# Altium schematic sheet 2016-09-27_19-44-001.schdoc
size 468 x 148 mm; SheetNumber: 1; SheetTotal: 1
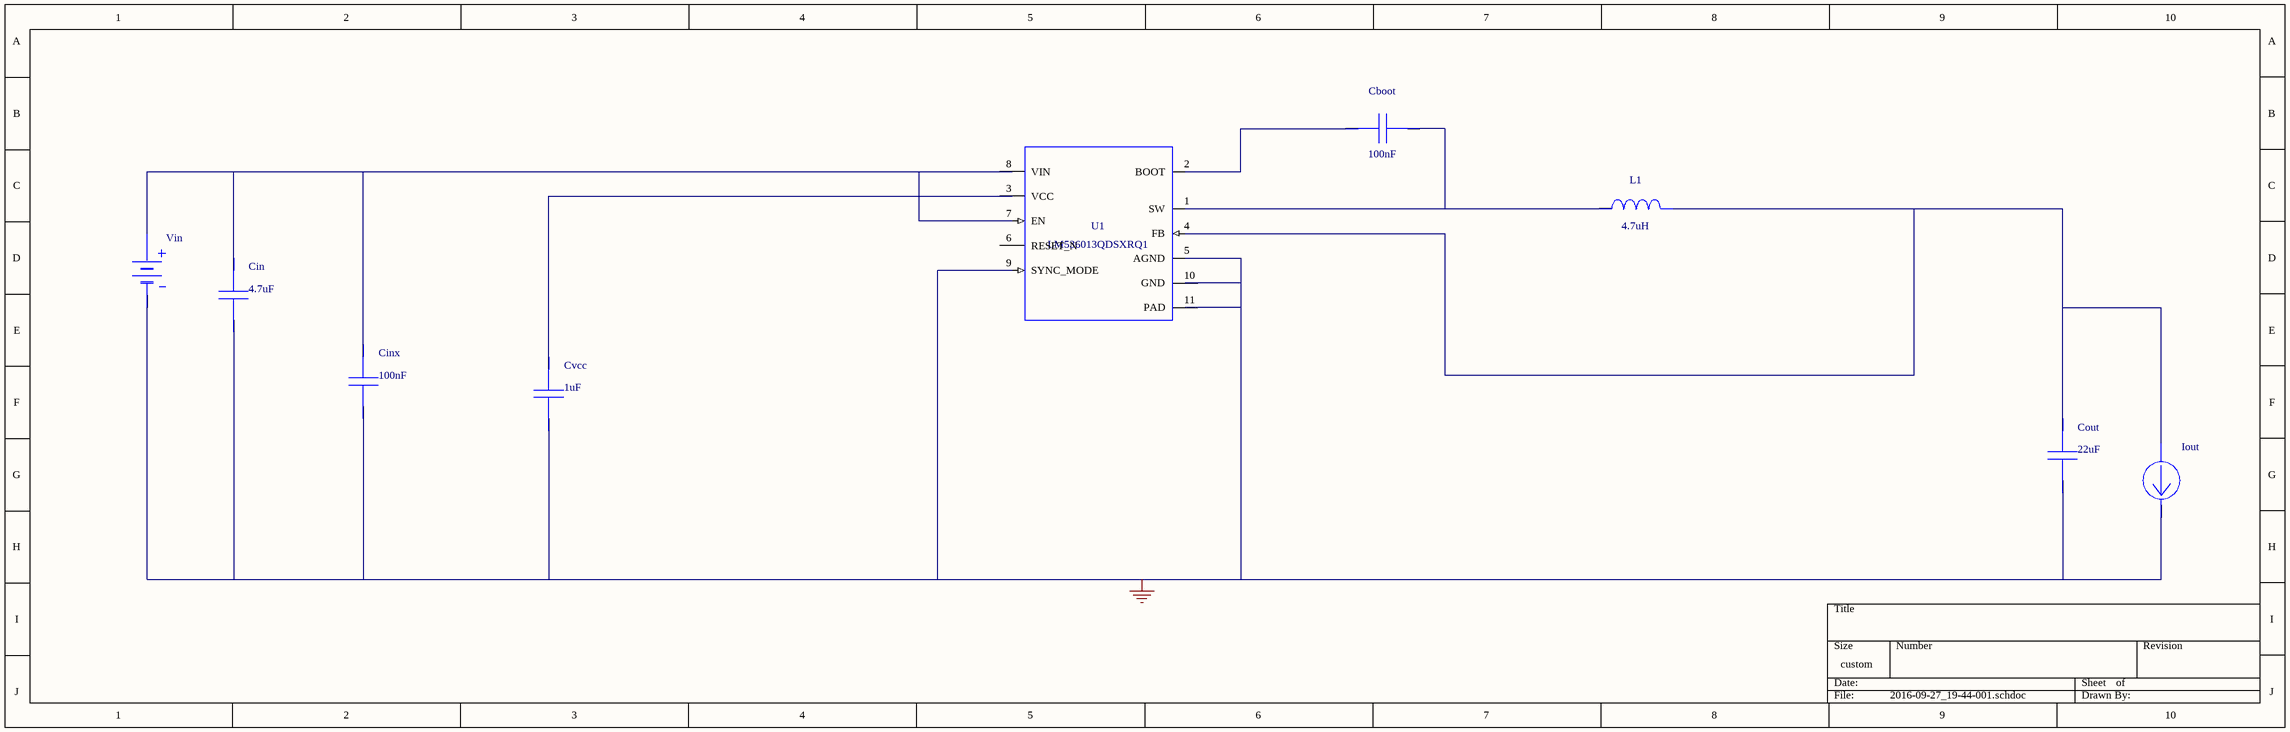
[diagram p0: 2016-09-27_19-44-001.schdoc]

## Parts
Cboot  value 100nF  (hidden comment: C0805C104K5RACTU)
Cin  value 4.7uF  (hidden comment: GRM32ER71H475KA88L)
Cinx  value 100nF  (hidden comment: 08055C104JAT2A)
Cout  value 22uF  (hidden comment: GRM32ER61C226ME20L)
Cvcc  value 1uF  (hidden comment: C1005X5R0J105M)
Iout  WB_CURRENT_LOAD  (value not drawn)
L1  value 4.7uH  (hidden comment: SDR0403-4R7ML)
U1  LM536013QDSXRQ1
Vin  WB_BATTERY  (value not drawn)

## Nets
0: Cin.2 Cinx.2 Cout.2 Cvcc.2 Iout.2(-) U1.5(AGND) U1.9(SYNC_MODE) U1.10(GND) U1.11(PAD) Vin.2(-)
NetCboot_1: Cboot.1 U1.2(BOOT)
NetCboot_2: Cboot.2 L1.1 U1.1(SW)
NetCin_1: Cin.1 Cinx.1 U1.7(EN) U1.8(VIN) Vin.1(+)
NetCout_1: Cout.1 Iout.1(+) L1.2 U1.4(FB)
NetCvcc_1: Cvcc.1 U1.3(VCC)

Not connected (* = marked no-connect by the designer): U1 6(RESET_N)

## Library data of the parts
Cboot = C0805C104K5RACTU: Manufacturer Name: Kemet
Cin = GRM32ER71H475KA88L: GRM32ER71H475KA8; Manufacturer Name: MuRata
Cinx = 08055C104JAT2A: Manufacturer Name: AVX
Cout = GRM32ER61C226ME20L: GRM32ER61C226ME2; Manufacturer Name: MuRata
Cvcc = C1005X5R0J105M: Manufacturer Name: TDK
L1 = SDR0403-4R7ML: Manufacturer Name: Bourns
U1 = LM536013QDSXRQ1: Manufacturer Name: Texas Instruments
